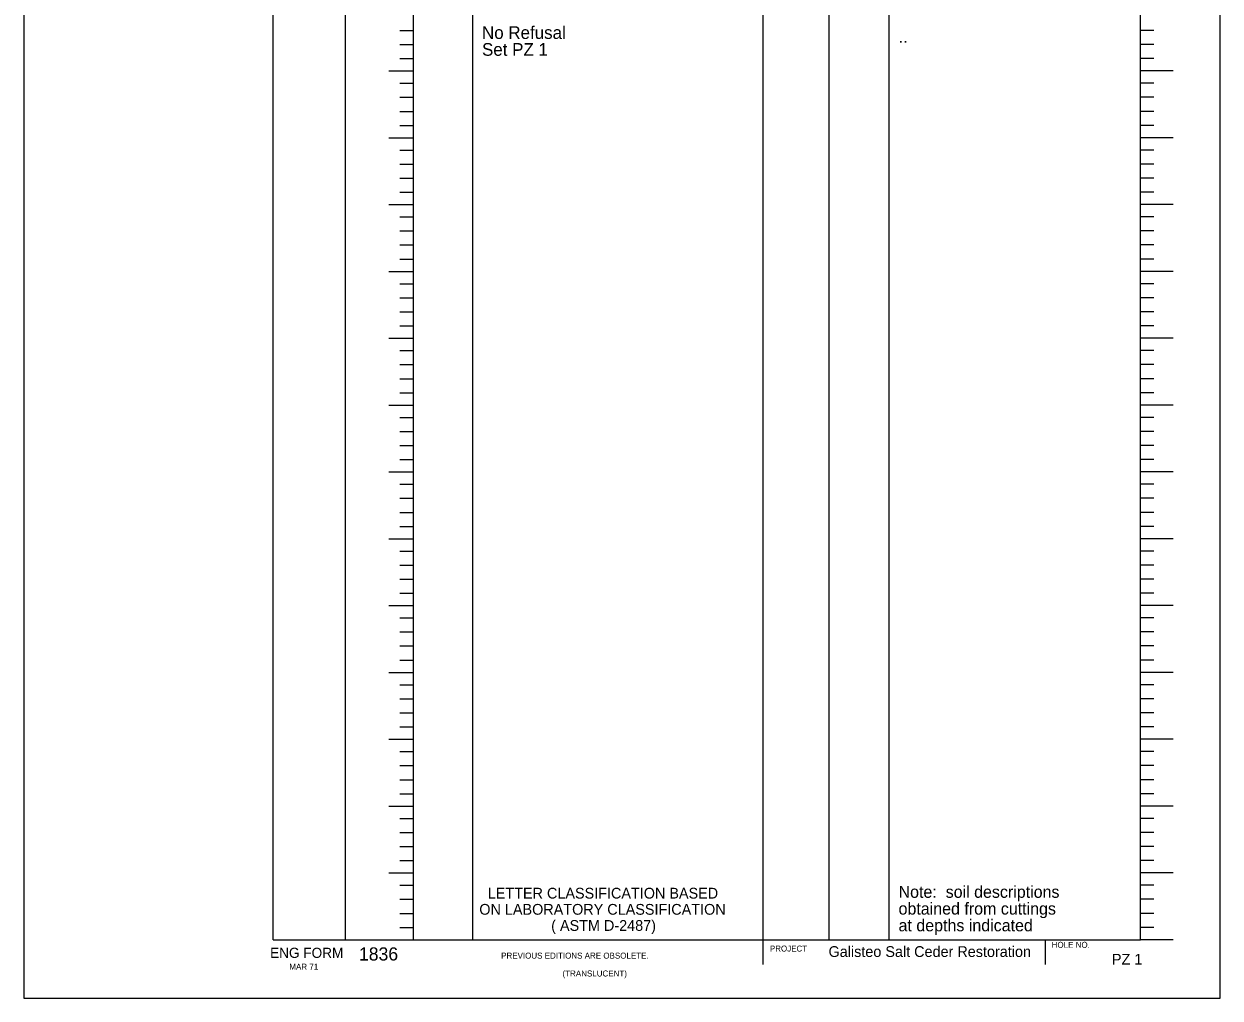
# Model space of a CAD drawing. Extents: x 0.1 to 0.8, y 0 to 1.17.
# Drawn here: x 0.096 to 0.805, y 0 to 0.577 of the extents above; entities that cross this region are included whole.
import ezdxf

# ---------------------------------------------------------------- set-up
doc = ezdxf.new("R2010")
doc.units = 0
for name, color, linetype in [('B-ANNO-NPLT', 7, 'Continuous'), ('B-LOGS-FDTA', 7, 'Continuous'), ('B-LOGS-FORM', 7, 'Continuous'), ('B-LOGS-LDTA', 7, 'Continuous')]:
    doc.layers.add(name, color=color, linetype=linetype)

msp = doc.modelspace()

# ---------------------------------------------------------------- linework, layer by layer
at = {"layer": 'B-ANNO-NPLT'}
msp.add_lwpolyline([(0.09631, -0.00026), (0.80465, -0.00026), (0.80465, 1.16641), (0.09631, 1.16641)], close=True, dxfattribs=at)
at = {"layer": 'B-LOGS-FORM'}
for p, q in [((0.24385, 0.03431), (0.24385, 1.13066)), ((0.75754, 0.03431), (0.75754, 1.13066)), ((0.28671, 0.03431), (0.28671, 0.937)), ((0.32695, 0.03431), (0.32695, 0.937)), ((0.36215, 0.03431), (0.36215, 0.937)), ((0.53414, 0.01958), (0.53414, 0.937)), ((0.57309, 0.03431), (0.57309, 0.937)), ((0.60872, 0.03431), (0.60872, 0.937)), ((0.31901, 0.57285), (0.32695, 0.57285)), ((0.76548, 0.57285), (0.75754, 0.57285)), ((0.31901, 0.56452), (0.32695, 0.56452)), ((0.76548, 0.56452), (0.75754, 0.56452)), ((0.31901, 0.55618), (0.32695, 0.55618)), ((0.76548, 0.55618), (0.75754, 0.55618)), ((0.31243, 0.5489), (0.32695, 0.5489)), ((0.77681, 0.5489), (0.75754, 0.5489)), ((0.31901, 0.5416), (0.32695, 0.5416)), ((0.76548, 0.5416), (0.75754, 0.5416)), ((0.31901, 0.53327), (0.32695, 0.53327)), ((0.76548, 0.53327), (0.75754, 0.53327)), ((0.31901, 0.52493), (0.32695, 0.52493)), ((0.76548, 0.52493), (0.75754, 0.52493)), ((0.31901, 0.5166), (0.32695, 0.5166)), ((0.76548, 0.5166), (0.75754, 0.5166)), ((0.31243, 0.50931), (0.32695, 0.50931)), ((0.77681, 0.50931), (0.75754, 0.50931)), ((0.31901, 0.50202), (0.32695, 0.50202)), ((0.76548, 0.50202), (0.75754, 0.50202)), ((0.31901, 0.49368), (0.32695, 0.49368)), ((0.76548, 0.49368), (0.75754, 0.49368)), ((0.31901, 0.48535), (0.32695, 0.48535)), ((0.76548, 0.48535), (0.75754, 0.48535)), ((0.31901, 0.47702), (0.32695, 0.47702)), ((0.76548, 0.47702), (0.75754, 0.47702)), ((0.31243, 0.46973), (0.32695, 0.46973)), ((0.77681, 0.46973), (0.75754, 0.46973)), ((0.31901, 0.46243), (0.32695, 0.46243)), ((0.76548, 0.46243), (0.75754, 0.46243)), ((0.31901, 0.4541), (0.32695, 0.4541)), ((0.76548, 0.4541), (0.75754, 0.4541)), ((0.31901, 0.44577), (0.32695, 0.44577)), ((0.76548, 0.44577), (0.75754, 0.44577)), ((0.31901, 0.43743), (0.32695, 0.43743)), ((0.76548, 0.43743), (0.75754, 0.43743)), ((0.31243, 0.43015), (0.32695, 0.43015)), ((0.77681, 0.43015), (0.75754, 0.43015)), ((0.31901, 0.42285), (0.32695, 0.42285)), ((0.76548, 0.42285), (0.75754, 0.42285)), ((0.31901, 0.41452), (0.32695, 0.41452)), ((0.76548, 0.41452), (0.75754, 0.41452)), ((0.31901, 0.40618), (0.32695, 0.40618)), ((0.76548, 0.40618), (0.75754, 0.40618)), ((0.31901, 0.39785), (0.32695, 0.39785)), ((0.76548, 0.39785), (0.75754, 0.39785)), ((0.31243, 0.39056), (0.32695, 0.39056)), ((0.77681, 0.39056), (0.75754, 0.39056)), ((0.31901, 0.38327), (0.32695, 0.38327)), ((0.76548, 0.38327), (0.75754, 0.38327)), ((0.31901, 0.37493), (0.32695, 0.37493)), ((0.76548, 0.37493), (0.75754, 0.37493)), ((0.31901, 0.3666), (0.32695, 0.3666)), ((0.76548, 0.3666), (0.75754, 0.3666)), ((0.31901, 0.35827), (0.32695, 0.35827)), ((0.76548, 0.35827), (0.75754, 0.35827)), ((0.31243, 0.35098), (0.32695, 0.35098)), ((0.77681, 0.35098), (0.75754, 0.35098)), ((0.31901, 0.34368), (0.32695, 0.34368)), ((0.76548, 0.34368), (0.75754, 0.34368)), ((0.31901, 0.33535), (0.32695, 0.33535)), ((0.76548, 0.33535), (0.75754, 0.33535)), ((0.31901, 0.32702), (0.32695, 0.32702)), ((0.76548, 0.32702), (0.75754, 0.32702)), ((0.31901, 0.31868), (0.32695, 0.31868)), ((0.76548, 0.31868), (0.75754, 0.31868)), ((0.31243, 0.3114), (0.32695, 0.3114)), ((0.77681, 0.3114), (0.75754, 0.3114)), ((0.31901, 0.3041), (0.32695, 0.3041)), ((0.76548, 0.3041), (0.75754, 0.3041)), ((0.31901, 0.29577), (0.32695, 0.29577)), ((0.76548, 0.29577), (0.75754, 0.29577)), ((0.31901, 0.28743), (0.32695, 0.28743)), ((0.76548, 0.28743), (0.75754, 0.28743)), ((0.31901, 0.2791), (0.32695, 0.2791)), ((0.76548, 0.2791), (0.75754, 0.2791)), ((0.31243, 0.27181), (0.32695, 0.27181)), ((0.77681, 0.27181), (0.75754, 0.27181)), ((0.31901, 0.26452), (0.32695, 0.26452)), ((0.76548, 0.26452), (0.75754, 0.26452)), ((0.31901, 0.25618), (0.32695, 0.25618)), ((0.76548, 0.25618), (0.75754, 0.25618)), ((0.31901, 0.24785), (0.32695, 0.24785)), ((0.76548, 0.24785), (0.75754, 0.24785)), ((0.31901, 0.23952), (0.32695, 0.23952)), ((0.76548, 0.23952), (0.75754, 0.23952)), ((0.31243, 0.23223), (0.32695, 0.23223)), ((0.77681, 0.23223), (0.75754, 0.23223)), ((0.31901, 0.22493), (0.32695, 0.22493)), ((0.76548, 0.22493), (0.75754, 0.22493)), ((0.31901, 0.2166), (0.32695, 0.2166)), ((0.76548, 0.2166), (0.75754, 0.2166)), ((0.31901, 0.20827), (0.32695, 0.20827)), ((0.76548, 0.20827), (0.75754, 0.20827)), ((0.31901, 0.19993), (0.32695, 0.19993)), ((0.76548, 0.19993), (0.75754, 0.19993)), ((0.31243, 0.19265), (0.32695, 0.19265)), ((0.77681, 0.19265), (0.75754, 0.19265)), ((0.31901, 0.18535), (0.32695, 0.18535)), ((0.76548, 0.18535), (0.75754, 0.18535)), ((0.31901, 0.17702), (0.32695, 0.17702)), ((0.76548, 0.17702), (0.75754, 0.17702)), ((0.31901, 0.16868), (0.32695, 0.16868)), ((0.76548, 0.16868), (0.75754, 0.16868)), ((0.31901, 0.16035), (0.32695, 0.16035)), ((0.76548, 0.16035), (0.75754, 0.16035)), ((0.31243, 0.15306), (0.32695, 0.15306)), ((0.77681, 0.15306), (0.75754, 0.15306)), ((0.31901, 0.14577), (0.32695, 0.14577)), ((0.76548, 0.14577), (0.75754, 0.14577)), ((0.31901, 0.13743), (0.32695, 0.13743)), ((0.76548, 0.13743), (0.75754, 0.13743)), ((0.31901, 0.1291), (0.32695, 0.1291)), ((0.76548, 0.1291), (0.75754, 0.1291)), ((0.31901, 0.12077), (0.32695, 0.12077)), ((0.76548, 0.12077), (0.75754, 0.12077)), ((0.31243, 0.11348), (0.32695, 0.11348)), ((0.77681, 0.11348), (0.75754, 0.11348)), ((0.31901, 0.10618), (0.32695, 0.10618)), ((0.76548, 0.10618), (0.75754, 0.10618)), ((0.31901, 0.09785), (0.32695, 0.09785)), ((0.76548, 0.09785), (0.75754, 0.09785)), ((0.31901, 0.08952), (0.32695, 0.08952)), ((0.76548, 0.08952), (0.75754, 0.08952)), ((0.31901, 0.08118), (0.32695, 0.08118)), ((0.76548, 0.08118), (0.75754, 0.08118)), ((0.31243, 0.0739), (0.32695, 0.0739)), ((0.77681, 0.0739), (0.75754, 0.0739)), ((0.31901, 0.0666), (0.32695, 0.0666)), ((0.76548, 0.0666), (0.75754, 0.0666)), ((0.31901, 0.05827), (0.32695, 0.05827)), ((0.76548, 0.05827), (0.75754, 0.05827)), ((0.31901, 0.04993), (0.32695, 0.04993)), ((0.76548, 0.04993), (0.75754, 0.04993)), ((0.31901, 0.0416), (0.32695, 0.0416)), ((0.76548, 0.0416), (0.75754, 0.0416)), ((0.24385, 0.03431), (0.75754, 0.03431)), ((0.70116, 0.03431), (0.70116, 0.01958)), ((0.77681, 0.03431), (0.75754, 0.03431))]:
    msp.add_line(p, q, dxfattribs=at)

# ---------------------------------------------------------------- texts
at = {"layer": 'B-LOGS-FDTA'}
for s, height, p in [('No Refusal', 0.0075, (0.36758, 0.56782)), ('Set PZ 1', 0.0075, (0.36758, 0.55784)), ('Note:  soil descriptions', 0.0070834, (0.61425, 0.05912)), ('obtained from cuttings', 0.0070834, (0.61425, 0.0492)), ('at depths indicated', 0.0070834, (0.61425, 0.03928)), ('Galisteo Salt Ceder Restoration', 0.006375, (0.57278, 0.0241)), ('PZ 1', 0.006375, (0.74058, 0.01954))]:
    msp.add_text(s, height=height, dxfattribs=at).set_placement(p)
at = {"layer": 'B-LOGS-FORM'}
for s, height, p in [('ENG FORM', 0.006021, (0.24208, 0.02354)), ('1836', 0.007791, (0.29472, 0.02199)), ('PROJECT', 0.003542, (0.53803, 0.0273)), ('HOLE NO.', 0.003542, (0.70492, 0.0295)), ('PREVIOUS EDITIONS ARE OBSOLETE.', 0.0035415, (0.37891, 0.02312)), ('MAR 71', 0.003542, (0.25349, 0.01653)), ('(TRANSLUCENT)', 0.0035415, (0.41526, 0.01253))]:
    msp.add_text(s, height=height, dxfattribs=at).set_placement(p)
at = {"layer": 'B-LOGS-LDTA'}
for s, height, p in [('..', 0.0075, (0.61426, 0.56551)), ('LETTER CLASSIFICATION BASED', 0.006375, (0.371, 0.05868)), ('ON LABORATORY CLASSIFICATION', 0.006375, (0.36598, 0.04911)), ('( ASTM D-2487)', 0.006375, (0.40854, 0.03955))]:
    msp.add_text(s, height=height, dxfattribs=at).set_placement(p)

doc.saveas('drawing.dxf')
